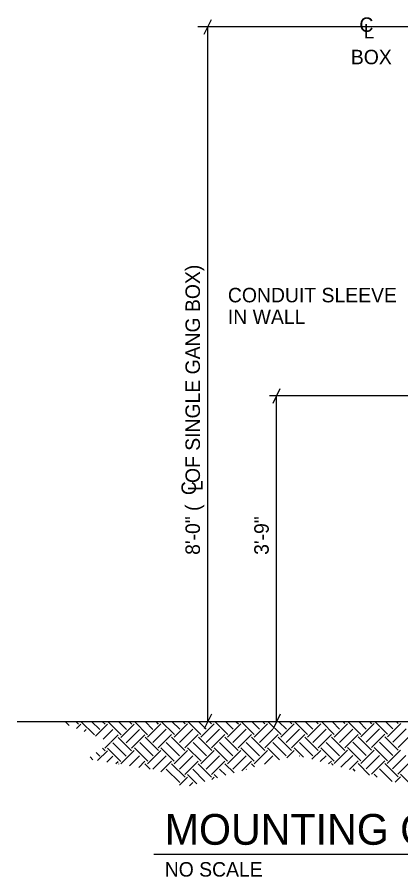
# Model space of a CAD drawing. Extents: x 10100.7 to 10147.8, y 10073.3 to 10116.8.
# Drawn here: x 10100.7 to 10118.35, y 10074.61 to 10114.21 of the extents above; entities that cross this region are included whole.
import ezdxf

# ---------------------------------------------------------------- set-up
doc = ezdxf.new("R2010")
doc.units = 0
for name, color, linetype in [('G-ANNO-TEXT', 7, 'Continuous'), ('Level 52', 7, 'Continuous'), ('Level 57', 7, 'Continuous'), ('Level 60', 7, 'Continuous'), ('Level 61', 7, 'Continuous'), ('Level 63', 7, 'Continuous')]:
    doc.layers.add(name, color=color, linetype=linetype)

msp = doc.modelspace()

# ---------------------------------------------------------------- linework, layer by layer
at = {"layer": 'Level 52'}
msp.add_line((10106.979, 10075.654), (10142.161, 10075.654), dxfattribs=at)
at = {"layer": 'Level 57'}
for p, q in [((10109.305, 10113.432), (10109.638, 10114.099)), ((10123.534, 10113.766), (10109.014, 10113.766)), ((10109.471, 10081.766), (10109.471, 10113.766)), ((10123.201, 10096.766), (10112.304, 10096.766)), ((10112.47, 10096.432), (10112.804, 10097.099)), ((10112.637, 10081.766), (10112.637, 10096.766)), ((10109.638, 10082.099), (10109.305, 10081.432)), ((10112.804, 10082.099), (10112.47, 10081.432))]:
    msp.add_line(p, q, dxfattribs=at)
at = {"layer": 'Level 60'}
for p, q in [((10102.897, 10081.771), (10103.093, 10081.575)), ((10103.39, 10081.77), (10103.518, 10081.642)), ((10103.509, 10081.765), (10103.514, 10081.77)), ((10103.632, 10081.765), (10104.246, 10081.15)), ((10104.119, 10081.769), (10104.492, 10081.396)), ((10104.611, 10081.768), (10104.737, 10081.642)), ((10104.737, 10081.765), (10104.74, 10081.767)), ((10104.867, 10081.767), (10105.479, 10081.155)), ((10105.359, 10081.766), (10105.725, 10081.401)), ((10105.851, 10081.765), (10105.97, 10081.646)), ((10106.088, 10081.765), (10106.699, 10081.155)), ((10106.581, 10081.764), (10106.944, 10081.4)), ((10107.073, 10081.763), (10107.19, 10081.646)), ((10107.328, 10081.763), (10107.932, 10081.159)), ((10107.82, 10081.762), (10108.177, 10081.405)), ((10108.313, 10081.761), (10108.423, 10081.651)), ((10108.55, 10081.76), (10109.151, 10081.159)), ((10109.042, 10081.759), (10109.397, 10081.405)), ((10109.534, 10081.758), (10109.643, 10081.65)), ((10109.79, 10081.758), (10110.384, 10081.164)), ((10110.282, 10081.757), (10110.63, 10081.409)), ((10110.774, 10081.756), (10110.876, 10081.655)), ((10111.011, 10081.756), (10111.604, 10081.163)), ((10111.504, 10081.755), (10111.849, 10081.409)), ((10111.996, 10081.754), (10112.095, 10081.655)), ((10112.251, 10081.753), (10112.837, 10081.168)), ((10112.744, 10081.752), (10113.082, 10081.414)), ((10113.236, 10081.751), (10113.328, 10081.659)), ((10113.473, 10081.751), (10114.056, 10081.168)), ((10113.965, 10081.75), (10114.302, 10081.413)), ((10114.458, 10081.749), (10114.548, 10081.659)), ((10114.713, 10081.749), (10115.289, 10081.172)), ((10115.205, 10081.748), (10115.535, 10081.418)), ((10115.698, 10081.747), (10115.781, 10081.664)), ((10115.935, 10081.746), (10116.509, 10081.172)), ((10116.427, 10081.745), (10116.755, 10081.418)), ((10116.919, 10081.744), (10117, 10081.663)), ((10117.175, 10081.744), (10117.742, 10081.176)), ((10117.667, 10081.743), (10117.988, 10081.422)), ((10118.159, 10081.742), (10118.233, 10081.668)), ((10103.431, 10081.441), (10103.632, 10081.642)), ((10103.783, 10081.302), (10103.877, 10081.396)), ((10104.305, 10081.095), (10104.856, 10081.646)), ((10104.657, 10080.955), (10105.101, 10081.4)), ((10105.47, 10081.032), (10106.084, 10081.646)), ((10105.716, 10080.786), (10106.33, 10081.4)), ((10106.694, 10081.036), (10107.308, 10081.65)), ((10106.94, 10080.79), (10107.554, 10081.405)), ((10107.923, 10081.036), (10108.537, 10081.65)), ((10108.168, 10080.79), (10108.783, 10081.405)), ((10109.147, 10081.04), (10109.761, 10081.655)), ((10109.393, 10080.795), (10110.007, 10081.409)), ((10110.375, 10081.04), (10110.99, 10081.655)), ((10110.621, 10080.795), (10111.235, 10081.409)), ((10111.599, 10081.045), (10112.214, 10081.659)), ((10111.845, 10080.799), (10112.459, 10081.413)), ((10112.828, 10081.045), (10113.442, 10081.659)), ((10113.074, 10080.799), (10113.688, 10081.413)), ((10114.052, 10081.049), (10114.666, 10081.663)), ((10114.298, 10080.803), (10114.912, 10081.418)), ((10115.281, 10081.049), (10115.895, 10081.663)), ((10115.526, 10080.803), (10116.14, 10081.418)), ((10116.505, 10081.053), (10117.119, 10081.668)), ((10116.75, 10080.808), (10117.365, 10081.422)), ((10117.733, 10081.053), (10118.347, 10081.668)), ((10117.979, 10080.808), (10118.593, 10081.422)), ((10105.008, 10080.816), (10105.347, 10081.155)), ((10105.347, 10081.032), (10105.961, 10080.418)), ((10105.961, 10080.54), (10106.576, 10081.155)), ((10106.58, 10081.036), (10107.194, 10080.422)), ((10107.186, 10080.545), (10107.8, 10081.159)), ((10107.8, 10081.036), (10108.414, 10080.422)), ((10108.414, 10080.545), (10109.028, 10081.159)), ((10109.033, 10081.041), (10109.647, 10080.426)), ((10109.638, 10080.549), (10110.252, 10081.163)), ((10110.252, 10081.04), (10110.867, 10080.426)), ((10110.867, 10080.549), (10111.481, 10081.163)), ((10111.485, 10081.045), (10112.1, 10080.431)), ((10112.091, 10080.553), (10112.705, 10081.168)), ((10112.705, 10081.045), (10113.319, 10080.431)), ((10113.319, 10080.553), (10113.934, 10081.168)), ((10113.938, 10081.049), (10114.552, 10080.435)), ((10114.543, 10080.558), (10115.158, 10081.172)), ((10115.158, 10081.049), (10115.772, 10080.435)), ((10115.772, 10080.558), (10116.386, 10081.172)), ((10116.391, 10081.054), (10117.005, 10080.439)), ((10116.996, 10080.562), (10117.61, 10081.176)), ((10117.61, 10081.053), (10118.225, 10080.439)), ((10118.225, 10080.562), (10118.839, 10081.176)), ((10104.622, 10080.537), (10104.742, 10080.418)), ((10104.733, 10080.54), (10104.992, 10080.799)), ((10104.856, 10080.54), (10105.47, 10079.926)), ((10105.102, 10080.786), (10105.716, 10080.172)), ((10106.089, 10080.545), (10106.703, 10079.931)), ((10106.335, 10080.791), (10106.949, 10080.176)), ((10107.308, 10080.545), (10107.923, 10079.931)), ((10107.554, 10080.79), (10108.168, 10080.176)), ((10108.541, 10080.549), (10109.156, 10079.935)), ((10108.787, 10080.795), (10109.401, 10080.181)), ((10109.761, 10080.549), (10110.375, 10079.935)), ((10110.007, 10080.795), (10110.621, 10080.181)), ((10110.994, 10080.554), (10111.608, 10079.939)), ((10111.24, 10080.799), (10111.854, 10080.185)), ((10112.214, 10080.553), (10112.767, 10080)), ((10112.459, 10080.799), (10113.074, 10080.185)), ((10113.447, 10080.558), (10113.878, 10080.127)), ((10113.692, 10080.804), (10114.307, 10080.189)), ((10114.666, 10080.558), (10115.281, 10079.943)), ((10114.912, 10080.803), (10115.526, 10080.189)), ((10115.899, 10080.562), (10116.514, 10079.948)), ((10116.145, 10080.808), (10116.759, 10080.194)), ((10117.119, 10080.562), (10117.733, 10079.948)), ((10117.365, 10080.808), (10117.979, 10080.193)), ((10104.335, 10080.334), (10104.496, 10080.172)), ((10104.399, 10079.96), (10104.856, 10080.418)), ((10104.821, 10079.891), (10105.101, 10080.172)), ((10105.466, 10079.808), (10106.08, 10080.422)), ((10105.868, 10079.719), (10106.326, 10080.176)), ((10106.694, 10079.808), (10107.308, 10080.422)), ((10106.94, 10079.562), (10107.554, 10080.176)), ((10107.918, 10079.812), (10108.533, 10080.426)), ((10108.164, 10079.566), (10108.778, 10080.181)), ((10109.147, 10079.812), (10109.761, 10080.426)), ((10109.393, 10079.566), (10110.007, 10080.181)), ((10110.371, 10079.816), (10110.985, 10080.431)), ((10110.617, 10079.571), (10111.231, 10080.185)), ((10111.599, 10079.816), (10112.214, 10080.431)), ((10112.073, 10079.799), (10112.459, 10080.185)), ((10113.099, 10080.096), (10113.438, 10080.435)), ((10113.676, 10080.182), (10113.684, 10080.189)), ((10114.254, 10080.023), (10114.666, 10080.435)), ((10114.64, 10079.917), (10114.912, 10080.189)), ((10115.276, 10079.825), (10115.89, 10080.439)), ((10115.596, 10079.654), (10116.136, 10080.193)), ((10116.505, 10079.825), (10117.119, 10080.439)), ((10116.75, 10079.579), (10117.365, 10080.193)), ((10117.729, 10079.829), (10118.343, 10080.443)), ((10117.975, 10079.584), (10118.589, 10080.198)), ((10104.047, 10080.13), (10104.181, 10079.996)), ((10105.242, 10079.822), (10105.347, 10079.926)), ((10105.352, 10079.808), (10105.357, 10079.803)), ((10106.29, 10079.649), (10106.571, 10079.931)), ((10106.571, 10079.808), (10106.816, 10079.563)), ((10107.313, 10079.444), (10107.8, 10079.931)), ((10107.804, 10079.812), (10108.419, 10079.198)), ((10108.41, 10079.321), (10109.024, 10079.935)), ((10109.024, 10079.812), (10109.638, 10079.198)), ((10109.638, 10079.321), (10110.252, 10079.935)), ((10110.257, 10079.817), (10110.679, 10079.395)), ((10111.036, 10079.498), (10111.477, 10079.939)), ((10111.477, 10079.816), (10111.624, 10079.669)), ((10115.025, 10079.811), (10115.158, 10079.943)), ((10115.162, 10079.825), (10115.234, 10079.753)), ((10115.982, 10079.548), (10116.382, 10079.948)), ((10116.382, 10079.825), (10116.916, 10079.291)), ((10116.996, 10079.334), (10117.61, 10079.948)), ((10117.615, 10079.829), (10118.229, 10079.215)), ((10118.22, 10079.338), (10118.834, 10079.952)), ((10107.559, 10079.567), (10108.173, 10078.952)), ((10108.778, 10079.566), (10109.338, 10079.006)), ((10110.011, 10079.571), (10110.298, 10079.284)), ((10111.231, 10079.571), (10111.243, 10079.558)), ((10116.136, 10079.579), (10116.238, 10079.477)), ((10117.369, 10079.584), (10117.946, 10079.007)), ((10108.171, 10078.836), (10108.533, 10079.198)), ((10108.533, 10079.321), (10108.957, 10078.896)), ((10108.627, 10078.8), (10108.778, 10078.952)), ((10109.652, 10079.097), (10109.757, 10079.202)), ((10109.766, 10079.325), (10109.917, 10079.174)), ((10117.123, 10079.338), (10117.268, 10079.194)), ((10118.094, 10078.966), (10118.343, 10079.215)), ((10118.343, 10079.338), (10118.95, 10078.731))]:
    msp.add_line(p, q, dxfattribs=at)
at = {"layer": 'Level 61'}
msp.add_line((10100.696, 10081.766), (10147.842, 10081.766), dxfattribs=at)

# ---------------------------------------------------------------- texts
at = {"layer": 'G-ANNO-TEXT'}
for s, p in [('C', (10116.445, 10113.531)), ('L', (10116.637, 10113.228))]:
    msp.add_text(s, height=0.667, dxfattribs=at).set_placement(p)
for s, p in [('L', (10109.228, 10092.383)), ('C', (10108.924, 10092.191))]:
    msp.add_text(s, height=0.667, rotation=90, dxfattribs=at).set_placement(p)
at = {"layer": 'Level 52'}
for s, height, p in [('MOUNTING OF #293SL TELEPHONE', 1.41667, (10107.485, 10076.086)), ('NO SCALE', 0.6667, (10107.485, 10074.619))]:
    msp.add_text(s, height=height, dxfattribs=at).set_placement(p)
at = {"layer": 'Level 63'}
for s, height, p in [('BOX', 0.6667, (10116.052, 10112.041)), ('CONDUIT SLEEVE', 0.66667, (10110.393, 10101.073)), ('IN WALL', 0.6667, (10110.393, 10100.073))]:
    msp.add_text(s, height=height, dxfattribs=at).set_placement(p)
for s, height, p in [('8\'-0" (    OF SINGLE GANG BOX)', 0.66667, (10109.107, 10089.44)), ('3\'-9"', 0.6667, (10112.273, 10089.44))]:
    msp.add_text(s, height=height, rotation=90, dxfattribs=at).set_placement(p)

doc.saveas('drawing.dxf')
